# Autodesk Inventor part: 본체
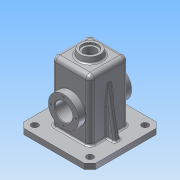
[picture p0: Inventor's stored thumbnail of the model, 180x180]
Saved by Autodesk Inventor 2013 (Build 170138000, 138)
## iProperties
Created: 2016-02
Part Number: 본체
Material: 알루미늄 6061
Document SubType Name: Modeling
Designer: user-11
Density: 2.71 g/cm^3
Mass: 932.866 g
Surface Area: 1043.41 cm^2
Volume: 344.231 cm^3
Author: user-11
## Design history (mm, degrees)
sketch "스케치1"
  geometry: L1 (60, 35)-(-60, 35); L2 (-60, 35)-(-60, -35); L3 (-60, -35)-(60, -35); L4 (60, -35)-(60, 35); 3 further points
  constraints: 8 end point, 2 midpoint, 2 parallel, 1 horizontal, 1 horizontal alignment, 1 perpendicular, 1 vertical alignment
  dimensions: "d0" = 70 distance of L3.end L1.start; "d2" = 120 distance of L2.end L3.end
extrude "돌출1" new body sketch "스케치1" stored distance "d3" = 70; taper "d4" = 0 deg
feature "쉘1" dims "d5" = 5
sketch "스케치2"
  geometry: L1 (0, 0)-(70, 0) reference; L2 (70, 70)-(70, 0) reference; L3 (0, 70)-(70, 70) reference; L4 (0, 0)-(0, 70) reference; L5 (65, 5)-(5, 5) reference; L6 (5, 5)-(5, 65) reference; L7 (5, 65)-(65, 65) reference; L8 (65, 65)-(65, 5) reference; L9 (0, 0)-(70, 0) reference; L10 (70, 70)-(70, 0) reference; L11 (0, 70)-(70, 70) reference; L12 (0, 0)-(0, 70) reference; L13 (100, 100)-(-30, 100); L14 (-30, 100)-(-30, -30); L15 (-30, -30)-(100, -30); L16 (100, -30)-(100, 100); 3 further points
  constraints: 8 end point, 2 midpoint, 2 parallel, 1 horizontal, 1 horizontal alignment, 1 perpendicular, 1 vertical alignment
  dimensions: "d6" = 130 distance of L15.end L13.start; "d8" = 130 distance of L14.end L15.end
extrude "돌출2" join sketch "스케치2" distance "d9" = 10; taper "d10" = 0 deg
sketch "스케치3"
  geometry: L1 (-5, 48.154)-(-5, -48.154); L2 (-60, 65)-(-60, -65) reference; L3 (-60, 30)-(55, 30) reference; L4 (22.5, 48)-(22.5, 30); L5 (22.5, 30)-(15.5, 23); L6 (15.5, 23)-(11, 23); L7 (11, 23)-(11, 48); L8 (11, 48)-(22.5, 48); L9 (-50, 35)-(60, 35) reference; 2 further points
  constraints: 12 end point, 4 perpendicular, 1 horizontal alignment, 1 midpoint, 1 point on line, 1 vertical
  dimensions: "d11" = 55 distance between parallel lines of L1 L2; "d12" = 55 diameter of L4 L1; "d13" = 32 diameter of L7 L1; "d14" = 135 deg angle of L3 L5; "d15" = 7 distance between parallel lines of L6 L3; "d16" = 13 distance between parallel lines of L8 L9
revolve "회전1" sketch "스케치3" stored, may be unused: angle "d17" = 90 deg
hole "구멍1" diameter "d20" = 32; stored, may be unused: countersink angle "d24" = 90 deg, drill point angle "d26" = 0 deg; dims "d18" = 10, "d19" = 10, "d21" = 6, "d22" = 4, "d23" = 2, "d25" = 48
fillet "모깎기1" dims "d27" = 8
sketch "스케치4"
  geometry: C1 r 27.5 at (0, 0) reference; 2 further points
  constraints: 1 vertical alignment
  dimensions: "d28" = 22.5 distance of point (0, 22.5) C1.centre
hole "구멍2" sketch "스케치4" at (0, 22.5) diameter "d29" = 3.242; stored, may be unused: countersink angle "d33" = 90 deg, drill point angle "d35" = 118 deg; dims "d30" = 8, "d31" = 4, "d32" = 2, "d34" = 10
fillet "모깎기2" dims "d39" = 0.5
sketch "스케치5"
  geometry: L1 (65, -60)-(65, -50) reference; L2 (65, -50)-(-65, -50) reference; L3 (35, 60)-(35, -50) reference; L4 (50, -50)-(35, 35.069); 1 further point
  constraints: 2 end point, 2 point on line
  dimensions: "d40" = 15 horizontal distance of L1.start L4.start; "d41" = 10 deg angle of L4 L1
feature "리브1" sketch "스케치5" dims "d42" = 1, "d43" = 10, "d44" = 0, "d45" = 0, "d46" = 1, "d47" = 1
sketch "스케치6"
  geometry: C1 r 20 at (27, -35); 1 further point
  constraints: 1 centre point, 1 coincident
  dimensions: "d48" = 40 diameter of C1
extrude "돌출3" join sketch "스케치6" distance "d50" = 10; taper "d51" = -10 deg
sketch "스케치7"
  geometry: C1 r 18.237 at (0, 0) reference; 1 further point
  constraints: 1 coincident
hole "구멍3" sketch "스케치7" at (0, 0) diameter "d52" = 21; stored, may be unused: countersink angle "d56" = 90 deg, drill point angle "d58" = 0 deg; dims "d53" = 8, "d54" = 28, "d55" = 4, "d57" = 15
sketch "스케치8"
  geometry: L1 (8.763, 10)-(45.237, 10) reference; A1 r 27.5 centre (27, -65) between (54, -59.78) and (0, -59.78) reference; 2 further points
  constraints: 1 vertical alignment, 1 other
  dimensions: "d59" = 30 distance from line of L1 point (27, -20)
feature "엠보싱1" sketch "스케치8" dims "d60" = 0.5, "d61" = 0
sketch "스케치9"
  geometry: L1 (100, 30)-(-30, 30) reference; L2 (-30, 30)-(-30, -100) reference; C1 r 6 at (-15, 15); 1 further point
  constraints: 1 centre point
  dimensions: "d62" = 15 distance from line of L1 C1.centre; "d63" = 15 distance from line of L2 C1.centre; "d64" = 12 diameter of C1
extrude "돌출4" cut sketch "스케치9" distance "d65" = 10; taper "d66" = 0 deg
chamfer "모따기1" distance "d73" = 10; stored, may be unused: second distance "d74" = 2, angle "d75" = 45 deg
chamfer "모따기2" distance "d76" = 1; stored, may be unused: second distance "d77" = 2, angle "d78" = 45 deg
fillet "모깎기3" dims "d79" = 3
fillet "모깎기4" dims "d80" = 3
fillet "모깎기5" dims "d81" = 3
fillet "모깎기6" dims "d82" = 3
fillet "모깎기7" dims "d83" = 3
fillet "모깎기8" dims "d84" = 3
fillet "모깎기9" dims "d85" = 8
fillet "모깎기10" dims "d86" = 3
fillet "모깎기11" dims "d87" = 3
fillet "모깎기12" dims "d88" = 0.5
fillet "모깎기13" dims "d89" = 0.5
node "솔리드1"
pattern_circular "원형 패턴1" dims angle "d37" = 360 deg
mirror "대칭1"
mirror "대칭2"
pattern_linear "직사각형 패턴1" dims "d69" = 100
node "투영된 루프1"
